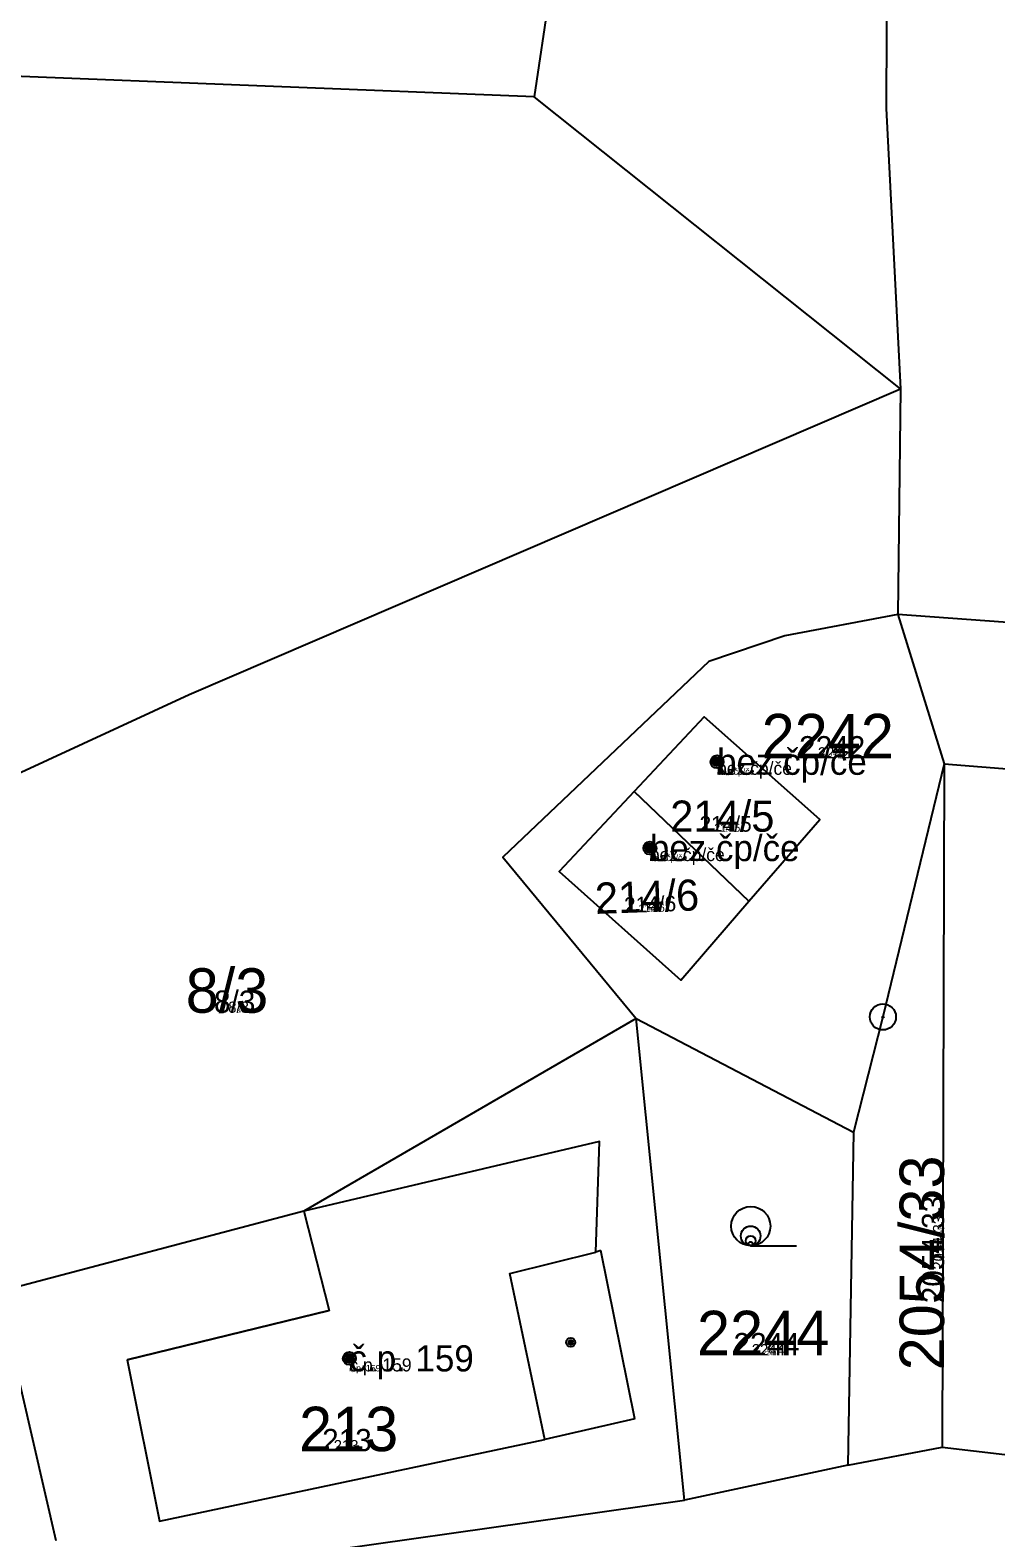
# Model space of a CAD drawing. Extents: x -744652 to -739090, y -980828 to -975855.
# Drawn here: x -742254.9 to -742218, y -978683.6 to -978626 of the extents above; entities that cross this region are included whole.
import ezdxf

# ---------------------------------------------------------------- set-up
doc = ezdxf.new("R2010")
doc.units = 0
for name, color, linetype in [('KAT_02_hranice parcel', 7, 'Continuous'), ('KAT_03_1000_st čísla parcelní', 7, 'Continuous'), ('KAT_03_1000_čísla parcelní', 7, 'Continuous'), ('KAT_03_1000_čísla popisná', 7, 'Continuous'), ('KAT_03_100_st čísla parcelní', 7, 'Continuous'), ('KAT_03_100_čísla parcelní', 7, 'Continuous'), ('KAT_03_100_čísla popisná', 7, 'Continuous'), ('KAT_03_250_st čísla parcelní', 7, 'Continuous'), ('KAT_03_250_čísla parcelní', 7, 'Continuous'), ('KAT_03_250_čísla popisná', 7, 'Continuous'), ('KAT_03_500_st čísla parcelní', 7, 'Continuous'), ('KAT_03_500_čísla parcelní', 7, 'Continuous'), ('KAT_03_500_čísla popisná', 7, 'Continuous'), ('KAT_04_vnitřní kresba', 7, 'Continuous'), ('KAT_05_1000_značky kultur', 7, 'Continuous'), ('KAT_05_100_značky kultur', 7, 'Continuous'), ('KAT_05_250_značky kultur', 7, 'Continuous'), ('KAT_05_500_značky kultur', 7, 'Continuous'), ('KAT_07_1000_značky budov', 7, 'Continuous'), ('KAT_07_100_značky budov', 7, 'Continuous'), ('KAT_07_500_značky budov', 7, 'Continuous'), ('KAT_11_značky bodu BP', 7, 'Continuous'), ('KAT_14_plocha_budovy', 7, 'Continuous')]:
    doc.layers.add(name, color=color, linetype=linetype)

msp = doc.modelspace()

# ---------------------------------------------------------------- linework, layer by layer
at = {"layer": 'KAT_02_hranice parcel'}
for p, q in [((-742233.61, -978614.94), (-742235.65, -978628.52)), ((-742235.65, -978628.52), (-742257.39, -978627.65)), ((-742221.64, -978639.69), (-742235.65, -978628.52)), ((-742221.64, -978639.69), (-742221.74, -978648.32)), ((-742221.74, -978648.32), (-742219.97, -978654.03)), ((-742219.97, -978654.03), (-742220.04, -978680.17)), ((-742231.82, -978655.09), (-742227.43, -978659.28)), ((-742229.9, -978682.2), (-742231.75, -978663.77)), ((-742231.75, -978663.77), (-742223.44, -978668.12)), ((-742223.44, -978668.12), (-742223.65, -978680.86)), ((-742253.92, -978683.75), (-742256.12, -978674.23)), ((-742223.65, -978680.86), (-742220.04, -978680.17)), ((-742223.65, -978680.86), (-742229.9, -978682.2)), ((-742249.16, -978684.92), (-742229.9, -978682.2))]:
    msp.add_line(p, q, dxfattribs=at)
for points in [[(-742219.81, -978615.31), (-742222.14, -978616.52), (-742222.18, -978628.96), (-742221.64, -978639.69)], [(-742261.17, -978657.08), (-742248.83, -978651.38), (-742221.64, -978639.69)], [(-742221.74, -978648.32), (-742226.06, -978649.14), (-742228.96, -978650.12), (-742236.84, -978657.6), (-742231.75, -978663.77)], [(-742219.97, -978654.03), (-742206.2, -978655.13), (-742206.49, -978649.43), (-742221.74, -978648.32)], [(-742227.43, -978659.28), (-742224.72, -978656.16), (-742229.14, -978652.23), (-742231.82, -978655.09)], [(-742219.97, -978654.03), (-742222.31, -978663.71), (-742223.44, -978668.12)], [(-742231.82, -978655.09), (-742234.69, -978658.15), (-742230.03, -978662.3), (-742227.43, -978659.28)], [(-742231.75, -978663.77), (-742244.45, -978671.14), (-742256.12, -978674.23)], [(-742220.04, -978680.17), (-742216.23, -978680.61), (-742203.29, -978681.51), (-742201.01, -978681.93), (-742194.91, -978683.52)]]:
    msp.add_lwpolyline(points, dxfattribs=at)
at = {"layer": 'KAT_03_1000_čísla popisná'}
for centre in [(-742228.65, -978653.95), (-742228.65, -978653.95), (-742231.22, -978657.25), (-742231.22, -978657.25), (-742242.71, -978676.77), (-742242.71, -978676.77)]:
    msp.add_circle(centre, 0.25, dxfattribs=at)
at = {"layer": 'KAT_03_100_čísla popisná'}
for centre in [(-742228.65, -978653.95), (-742228.65, -978653.95), (-742231.22, -978657.25), (-742231.22, -978657.25), (-742242.71, -978676.77), (-742242.71, -978676.77)]:
    msp.add_circle(centre, 0.025, dxfattribs=at)
at = {"layer": 'KAT_03_250_čísla popisná'}
for centre in [(-742228.65, -978653.95), (-742228.65, -978653.95), (-742231.22, -978657.25), (-742231.22, -978657.25), (-742242.71, -978676.77), (-742242.71, -978676.77)]:
    msp.add_circle(centre, 0.0625, dxfattribs=at)
at = {"layer": 'KAT_03_500_čísla popisná'}
for centre in [(-742228.65, -978653.95), (-742228.65, -978653.95), (-742231.22, -978657.25), (-742231.22, -978657.25), (-742242.71, -978676.77), (-742242.71, -978676.77)]:
    msp.add_circle(centre, 0.125, dxfattribs=at)
at = {"layer": 'KAT_04_vnitřní kresba'}
for p, q in [((-742233.14, -978668.47), (-742244.45, -978671.14)), ((-742233.29, -978672.71), (-742233.14, -978668.47)), ((-742244.45, -978671.14), (-742243.48, -978674.94)), ((-742236.58, -978673.52), (-742233.29, -978672.71)), ((-742233.09, -978672.64), (-742233.29, -978672.71)), ((-742231.8, -978679.08), (-742233.09, -978672.64)), ((-742235.23, -978679.87), (-742236.58, -978673.52)), ((-742251.21, -978676.83), (-742243.48, -978674.94)), ((-742251.21, -978676.83), (-742249.97, -978683)), ((-742231.8, -978679.08), (-742235.23, -978679.87)), ((-742249.97, -978683), (-742235.23, -978679.87))]:
    msp.add_line(p, q, dxfattribs=at)
at = {"layer": 'KAT_05_1000_značky kultur'}
msp.add_line((-742227.363, -978672.46), (-742225.613, -978672.46), dxfattribs=at)
msp.add_circle((-742227.363, -978671.71), 0.75, dxfattribs=at)
at = {"layer": 'KAT_05_100_značky kultur'}
msp.add_line((-742227.369, -978672.46), (-742227.194, -978672.46), dxfattribs=at)
msp.add_circle((-742227.369, -978672.385), 0.075, dxfattribs=at)
at = {"layer": 'KAT_05_250_značky kultur'}
msp.add_line((-742227.368, -978672.46), (-742226.931, -978672.46), dxfattribs=at)
msp.add_circle((-742227.368, -978672.272), 0.187, dxfattribs=at)
at = {"layer": 'KAT_05_500_značky kultur'}
msp.add_line((-742227.367, -978672.46), (-742226.492, -978672.46), dxfattribs=at)
msp.add_circle((-742227.366, -978672.085), 0.375, dxfattribs=at)
at = {"layer": 'KAT_07_1000_značky budov'}
for centre in [(-742228.657, -978653.949), (-742231.227, -978657.249), (-742234.247, -978676.159), (-742242.717, -978676.769)]:
    msp.add_circle(centre, 0.175, dxfattribs=at)
at = {"layer": 'KAT_07_100_značky budov'}
for centre in [(-742228.651, -978653.95), (-742231.221, -978657.25), (-742234.241, -978676.16), (-742242.711, -978676.77)]:
    msp.add_circle(centre, 0.0175, dxfattribs=at)
at = {"layer": 'KAT_07_500_značky budov'}
for centre, radius in [((-742228.653, -978653.95), 0.0875), ((-742228.652, -978653.95), 0.0438), ((-742231.223, -978657.25), 0.0875), ((-742231.222, -978657.25), 0.0438), ((-742234.243, -978676.16), 0.0875), ((-742234.242, -978676.16), 0.0438), ((-742242.713, -978676.77), 0.0875), ((-742242.712, -978676.77), 0.0438)]:
    msp.add_circle(centre, radius, dxfattribs=at)
at = {"layer": 'KAT_11_značky bodu BP'}
for radius in [0.5, 0.0303]:
    msp.add_circle((-742222.31, -978663.71), radius, dxfattribs=at)
at = {"layer": 'KAT_14_plocha_budovy'}
for points in [[(-742221.74, -978648.32), (-742219.97, -978654.03), (-742206.2, -978655.13), (-742206.49, -978649.43)], [(-742231.82, -978655.09), (-742227.43, -978659.28), (-742224.72, -978656.16), (-742229.14, -978652.23)], [(-742231.82, -978655.09), (-742234.69, -978658.15), (-742230.03, -978662.3), (-742227.43, -978659.28)], [(-742251.21, -978676.83), (-742249.97, -978683), (-742235.23, -978679.87), (-742236.58, -978673.52), (-742233.29, -978672.71), (-742233.14, -978668.47), (-742244.45, -978671.14), (-742243.48, -978674.94)]]:
    msp.add_lwpolyline(points, close=True, dxfattribs=at)

# ---------------------------------------------------------------- texts
at = {"layer": 'KAT_03_1000_st čísla parcelní'}
for s, height, p in [('214/5', 1.19, (-742230.441, -978656.625)), ('213', 1.7, (-742244.634, -978680.32))]:
    msp.add_text(s, height=height, dxfattribs=at).set_placement(p)
msp.add_text('214/6', height=1.19, rotation=2, dxfattribs=at).set_placement((-742233.299, -978659.772))
at = {"layer": 'KAT_03_1000_čísla parcelní'}
for s, p in [('2242', (-742226.947, -978653.82)), ('8/3', (-742248.968, -978663.55)), ('2244', (-742229.417, -978676.65))]:
    msp.add_text(s, height=1.7, dxfattribs=at).set_placement(p)
msp.add_text('2054/33', height=1.7, rotation=90, dxfattribs=at).set_placement((-742219.97, -978677.228))
at = {"layer": 'KAT_03_1000_čísla popisná'}
for s, height, p in [('bez čp/če', 1, (-742228.65, -978654.45)), ('bez čp/če', 1, (-742231.22, -978657.75)), ('214/5', 0.0119, (-742228.219, -978656.625)), ('č.p. 159', 1, (-742242.71, -978677.27)), ('213', 0.017, (-742242.885, -978680.32))]:
    msp.add_text(s, height=height, dxfattribs=at).set_placement(p)
msp.add_text('214/6', height=0.0119, rotation=2, dxfattribs=at).set_placement((-742231.111, -978659.696))
at = {"layer": 'KAT_03_100_st čísla parcelní'}
for s, height, p in [('214/5', 0.119, (-742228.421, -978656.625)), ('213', 0.17, (-742243.044, -978680.32))]:
    msp.add_text(s, height=height, dxfattribs=at).set_placement(p)
msp.add_text('214/6', height=0.119, rotation=2, dxfattribs=at).set_placement((-742231.31, -978659.703))
at = {"layer": 'KAT_03_100_čísla parcelní'}
for s, p in [('2242', (-742224.369, -978653.82)), ('8/3', (-742247.016, -978663.55)), ('2244', (-742226.905, -978676.65))]:
    msp.add_text(s, height=0.17, dxfattribs=at).set_placement(p)
msp.add_text('2054/33', height=0.17, rotation=90, dxfattribs=at).set_placement((-742219.97, -978672.608))
at = {"layer": 'KAT_03_100_čísla popisná'}
for s, height, p in [('bez čp/če', 0.1, (-742228.65, -978654.45)), ('214/5', 0.00119, (-742228.199, -978656.625)), ('bez čp/če', 0.1, (-742231.22, -978657.75)), ('č.p. 159', 0.1, (-742242.71, -978677.27)), ('213', 0.0017, (-742242.869, -978680.32))]:
    msp.add_text(s, height=height, dxfattribs=at).set_placement(p)
msp.add_text('214/6', height=0.00119, rotation=2, dxfattribs=at).set_placement((-742231.091, -978659.695))
at = {"layer": 'KAT_03_250_st čísla parcelní'}
for s, height, p in [('214/5', 0.2975, (-742228.758, -978656.625)), ('213', 0.425, (-742243.309, -978680.32))]:
    msp.add_text(s, height=height, dxfattribs=at).set_placement(p)
msp.add_text('214/6', height=0.2975, rotation=2, dxfattribs=at).set_placement((-742231.642, -978659.714))
at = {"layer": 'KAT_03_250_čísla parcelní'}
for s, p in [('2242', (-742224.799, -978653.82)), ('8/3', (-742247.342, -978663.55)), ('2244', (-742227.324, -978676.65))]:
    msp.add_text(s, height=0.425, dxfattribs=at).set_placement(p)
msp.add_text('2054/33', height=0.425, rotation=90, dxfattribs=at).set_placement((-742219.97, -978673.378))
at = {"layer": 'KAT_03_250_čísla popisná'}
for s, height, p in [('bez čp/če', 0.25, (-742228.65, -978654.45)), ('214/5', 0.00297, (-742228.203, -978656.625)), ('bez čp/če', 0.25, (-742231.22, -978657.75)), ('č.p. 159', 0.25, (-742242.71, -978677.27)), ('213', 0.00425, (-742242.872, -978680.32))]:
    msp.add_text(s, height=height, dxfattribs=at).set_placement(p)
msp.add_text('214/6', height=0.00297, rotation=2, dxfattribs=at).set_placement((-742231.095, -978659.695))
at = {"layer": 'KAT_03_500_st čísla parcelní'}
for s, height, p in [('214/5', 0.595, (-742229.319, -978656.625)), ('213', 0.85, (-742243.751, -978680.32))]:
    msp.add_text(s, height=height, dxfattribs=at).set_placement(p)
msp.add_text('214/6', height=0.595, rotation=2, dxfattribs=at).set_placement((-742232.194, -978659.733))
at = {"layer": 'KAT_03_500_čísla parcelní'}
for s, p in [('2242', (-742225.515, -978653.82)), ('8/3', (-742247.884, -978663.55)), ('2244', (-742228.022, -978676.65))]:
    msp.add_text(s, height=0.85, dxfattribs=at).set_placement(p)
msp.add_text('2054/33', height=0.85, rotation=90, dxfattribs=at).set_placement((-742219.97, -978674.661))
at = {"layer": 'KAT_03_500_čísla popisná'}
for s, height, p in [('bez čp/če', 0.5, (-742228.65, -978654.45)), ('214/5', 0.00595, (-742228.208, -978656.625)), ('bez čp/če', 0.5, (-742231.22, -978657.75)), ('č.p. 159', 0.5, (-742242.71, -978677.27)), ('213', 0.0085, (-742242.876, -978680.32))]:
    msp.add_text(s, height=height, dxfattribs=at).set_placement(p)
msp.add_text('214/6', height=0.00595, rotation=2, dxfattribs=at).set_placement((-742231.1, -978659.695))

doc.saveas('drawing.dxf')
